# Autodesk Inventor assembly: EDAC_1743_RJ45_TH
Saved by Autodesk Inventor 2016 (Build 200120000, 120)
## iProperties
Created: 2018-05
Part Number: EDAC_1743_RJ45_TH
Document SubType Name: Assembly
Designer: Administrator
Title: EDAC_1743_RJ45_TH v18
Author: Administrator
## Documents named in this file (5)
- c:\worker\convert-fusion-mar-2018\tmp\job-1\16\output\files\8c58ff39-88bb-4352-afd9-60265520bae5\EDAC_1743_RJ45_TH v18.iam
- c:\worker\convert-fusion-mar-2018\tmp\job-1\16\output\files\8c58ff39-88bb-4352-afd9-60265520bae5\shell_1.ipt
- c:\worker\convert-fusion-mar-2018\tmp\job-1\16\output\files\8c58ff39-88bb-4352-afd9-60265520bae5\wiring.iam
- c:\worker\convert-fusion-mar-2018\tmp\job-1\16\output\files\8c58ff39-88bb-4352-afd9-60265520bae5\base_1.ipt
- c:\worker\convert-fusion-mar-2018\tmp\job-1\16\output\files\8c58ff39-88bb-4352-afd9-60265520bae5\lights.iam
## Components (4 placed, 4 different names)
1. shell:1
2. wiring:1 [sub-assembly]
3. base:1
4. lights:1 [sub-assembly]
